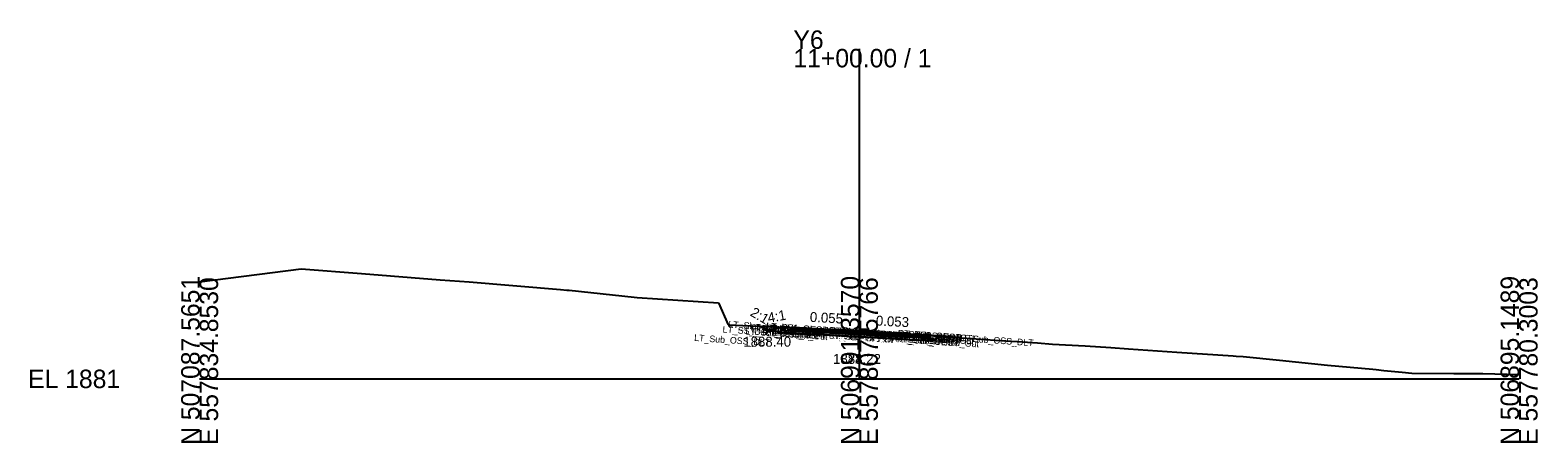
# Model space of a CAD drawing. Extents: x -26 to 203, y -10 to 1539.
# Drawn here: x -25.7 to 202.8, y 990.3 to 1052.8 of the extents above; entities that cross this region are included whole.
import ezdxf

# ---------------------------------------------------------------- set-up
doc = ezdxf.new("R2010")
doc.units = 0
for name, color, linetype in [('Default', 7, 'Continuous'), ('Exist Cross Section Cell', 7, 'Continuous'), ('Exist XS Center Line Elevation Label', 7, 'Continuous'), ('Exist XS Ground Line', 7, 'Continuous'), ('Prop CMT Pvmt Course 1', 7, 'Continuous'), ('Prop CMT Pvmt Course 2', 7, 'Continuous'), ('Prop CMT Pvmt Course 3', 7, 'Continuous'), ('Prop CMT Pvmt Surface', 7, 'Continuous'), ('Prop CMT Pvmt Surface Shoulder', 7, 'Continuous'), ('Prop CMT Shld Paved Course 1', 7, 'Continuous'), ('Prop CMT Shld Paved Course 2', 7, 'Continuous'), ('Prop CMT Shld Paved Course 3', 7, 'Continuous'), ('Prop CMT Slope Grass', 7, 'Continuous'), ('Prop CMT Subgrade Earthwork', 7, 'Continuous'), ('Prop XS Ditch Standard Text', 7, 'Continuous'), ('Prop XS Earthwork Shape', 7, 'Continuous'), ('Prop XS SE Text', 7, 'Continuous'), ('Prop XS Side Slope Text', 7, 'Continuous'), ('Typical Text Asphalt at Bridge Approach CELL', 7, 'Continuous')]:
    doc.layers.add(name, color=color, linetype=linetype)

msp = doc.modelspace()

# ---------------------------------------------------------------- linework, layer by layer
at = {"layer": 'Exist Cross Section Cell'}
for p, q in [((100, 1000), (100, 1050.01)), ((0, 1000), (100, 1000)), ((100, 1000), (200, 1000))]:
    msp.add_line(p, q, dxfattribs=at)
at = {"layer": 'Exist XS Ground Line'}
for p, q in [((0, 1014.72), (15.4, 1016.67)), ((15.4, 1016.67), (24.54, 1015.96)), ((24.54, 1015.96), (36.44, 1015.02)), ((36.44, 1015.02), (40.83, 1014.73)), ((40.83, 1014.73), (54.7, 1013.53)), ((54.7, 1013.53), (55.67, 1013.44)), ((55.67, 1013.44), (56, 1013.42)), ((56, 1013.42), (65.84, 1012.37)), ((65.84, 1012.37), (66.3, 1012.34)), ((66.3, 1012.34), (78.67, 1011.55)), ((78.67, 1011.55), (80.12, 1008.19)), ((80.12, 1008.19), (83.42, 1008.02)), ((83.42, 1008.02), (88.9, 1007.83)), ((88.9, 1007.83), (89.89, 1007.8)), ((89.89, 1007.8), (98.34, 1007.32)), ((98.34, 1007.32), (100, 1007.22)), ((100, 1007.22), (101.07, 1007.16)), ((101.07, 1007.16), (104.32, 1007.01)), ((104.32, 1007.01), (106.3, 1006.88)), ((106.3, 1006.88), (119.14, 1005.99)), ((119.14, 1005.99), (120.56, 1005.88)), ((120.56, 1005.88), (121.39, 1005.81)), ((121.39, 1005.81), (124.71, 1005.6)), ((124.71, 1005.6), (127, 1005.44)), ((127, 1005.44), (129.25, 1005.27)), ((129.25, 1005.27), (134.24, 1004.99)), ((134.24, 1004.99), (138.09, 1004.74)), ((138.09, 1004.74), (140.78, 1004.55)), ((140.78, 1004.55), (148.1, 1004.06)), ((148.1, 1004.06), (156.66, 1003.48)), ((156.66, 1003.48), (157.11, 1003.45)), ((157.11, 1003.45), (158.19, 1003.39)), ((158.19, 1003.39), (163.66, 1002.82)), ((163.66, 1002.82), (166.1, 1002.57)), ((166.1, 1002.57), (170.97, 1002.1)), ((170.97, 1002.1), (177.82, 1001.46)), ((177.82, 1001.46), (178.32, 1001.41)), ((178.32, 1001.41), (179.47, 1001.29)), ((179.47, 1001.29), (182.29, 1001)), ((182.29, 1001), (183.73, 1000.86)), ((183.73, 1000.86), (190.09, 1000.84)), ((190.09, 1000.84), (194.52, 1000.84)), ((194.52, 1000.84), (200, 1000.68))]:
    msp.add_line(p, q, dxfattribs=at)
at = {"layer": 'Prop CMT Pvmt Course 1'}
for points in [[(100, 1007.23), (90, 1007.79)], [(90, 1007.79), (90, 1007.54)], [(90, 1007.54), (100, 1006.98)], [(100, 1006.98), (100, 1007.23)], [(100, 1007.23), (110, 1006.7)], [(100, 1006.98), (100, 1007.23)], [(110, 1006.45), (100, 1006.98)], [(110, 1006.7), (110, 1006.45)]]:
    msp.add_lwpolyline(points, dxfattribs=at)
msp.add_lwpolyline([(100, 1006.98), (100, 1007.11), (100, 1007.11), (100, 1006.98)], close=True, dxfattribs=at)
msp.add_lwpolyline([(100, 1006.98), (100, 1007.11), (100, 1007.11), (100, 1006.98)], close=True, dxfattribs=at)
at = {"layer": 'Prop CMT Pvmt Course 2'}
for points in [[(100, 1006.98), (90, 1007.54)], [(90, 1007.54), (90, 1007.29)], [(90, 1007.29), (100, 1006.73)], [(100, 1006.73), (100, 1006.98)], [(100, 1006.73), (100, 1006.98)], [(100, 1006.98), (110, 1006.45)], [(110, 1006.2), (100, 1006.73)], [(110, 1006.45), (110, 1006.2)]]:
    msp.add_lwpolyline(points, dxfattribs=at)
at = {"layer": 'Prop CMT Pvmt Course 3'}
for points in [[(100, 1006.73), (90, 1007.29)], [(90, 1007.29), (90, 1006.91)], [(90, 1006.91), (100, 1006.36)], [(100, 1006.36), (100, 1006.73)], [(100, 1006.73), (110, 1006.2)], [(100, 1006.36), (100, 1006.73)], [(110, 1005.82), (100, 1006.36)], [(110, 1006.2), (110, 1005.82)]]:
    msp.add_lwpolyline(points, dxfattribs=at)
at = {"layer": 'Prop CMT Pvmt Surface'}
for points in [[(100, 1007.23), (90, 1007.79)], [(100, 1007.23), (110, 1006.7)]]:
    msp.add_lwpolyline(points, dxfattribs=at)
at = {"layer": 'Prop CMT Pvmt Surface Shoulder'}
for points in [[(90, 1007.79), (90, 1007.79)], [(110, 1006.7), (110, 1006.7)]]:
    msp.add_lwpolyline(points, dxfattribs=at)
at = {"layer": 'Prop CMT Shld Paved Course 1'}
for points in [[(90.06, 1007.78), (89.79, 1007.55)], [(89.79, 1007.55), (90.04, 1007.54)], [(90, 1007.79), (90, 1007.79)], [(90, 1007.54), (90, 1007.79)], [(110, 1006.7), (110, 1006.7)], [(110, 1006.7), (110.26, 1006.44)], [(110, 1006.45), (110, 1006.7)], [(110.26, 1006.44), (110, 1006.45)]]:
    msp.add_lwpolyline(points, dxfattribs=at)
at = {"layer": 'Prop CMT Shld Paved Course 2'}
for points in [[(90.04, 1007.54), (89.79, 1007.55), (89.52, 1007.31)], [(89.52, 1007.31), (90.03, 1007.29)], [(90, 1007.29), (90, 1007.54)], [(110, 1006.45), (110.26, 1006.44), (110.51, 1006.19)], [(110, 1006.2), (110, 1006.45)], [(110.51, 1006.19), (110, 1006.2)]]:
    msp.add_lwpolyline(points, dxfattribs=at)
at = {"layer": 'Prop CMT Shld Paved Course 3'}
for points in [[(90.03, 1007.29), (89.52, 1007.31), (89.02, 1007.33), (88.61, 1006.98)], [(88.61, 1006.98), (90, 1006.91)], [(90, 1006.91), (90, 1007.29)], [(110, 1006.2), (110.51, 1006.19), (111.01, 1006.18), (111.39, 1005.8)], [(110, 1005.82), (110, 1006.2)], [(111.39, 1005.8), (110, 1005.82)]]:
    msp.add_lwpolyline(points, dxfattribs=at)
at = {"layer": 'Prop CMT Slope Grass'}
msp.add_line((110, 1006.7), (112.33, 1006.46), dxfattribs=at)
msp.add_lwpolyline([(90.06, 1007.78), (88.05, 1007.76), (86.02, 1007.4), (85.07, 1007.96)], dxfattribs=at)
at = {"layer": 'Prop CMT Subgrade Earthwork'}
for p, q in [((88.61, 1006.98), (86.02, 1007.4)), ((111.39, 1005.8), (112.33, 1006.46))]:
    msp.add_line(p, q, dxfattribs=at)
for points in [[(90, 1006.91), (88.61, 1006.98)], [(100, 1006.36), (90, 1006.91)], [(100, 1006.36), (110, 1005.82)], [(110, 1005.82), (111.39, 1005.8)]]:
    msp.add_lwpolyline(points, dxfattribs=at)
at = {"layer": 'Prop XS Earthwork Shape'}
for points in [[(88.05, 1007.76), (86.02, 1007.4), (85.07, 1007.96), (88.9, 1007.83), (89.89, 1007.8), (90, 1007.79)], [(88.05, 1007.76), (86.02, 1007.4), (88.61, 1006.98), (90, 1006.91), (100, 1006.36), (110, 1005.82), (111.39, 1005.8), (112.33, 1006.46), (106.3, 1006.88), (104.75, 1006.98), (103.54, 1007.04), (101.07, 1007.16), (100, 1007.23), (98.34, 1007.32), (90, 1007.79)], [(104.32, 1007.01), (104.75, 1006.98), (103.54, 1007.04)]]:
    msp.add_lwpolyline(points, close=True, dxfattribs=at)

# ---------------------------------------------------------------- texts
at = {"layer": 'Default'}
msp.add_text('-', height=0.0001, dxfattribs=at).set_placement((0, 1000))
at = {"layer": 'Exist Cross Section Cell'}
for s, p in [('Y6', (90, 1050.01)), ('11+00.00 / 1', (90, 1047.21)), ('EL 1881', (-26, 998.6))]:
    msp.add_text(s, height=2.8, dxfattribs=at).set_placement(p)
for s, p in [('N 507087.5651', (0, 990)), ('E 557834.8530', (2.8, 990)), ('N 506991.3570', (100, 990)), ('E 557807.5766', (102.8, 990)), ('N 506895.1489', (200, 990)), ('E 557780.3003', (202.8, 990))]:
    msp.add_text(s, height=2.8, rotation=90, dxfattribs=at).set_placement(p)
at = {"layer": 'Exist XS Center Line Elevation Label'}
msp.add_text('1888.22', height=1.5, dxfattribs=at).set_placement((96.01, 1002.27))
at = {"layer": 'Prop XS Ditch Standard Text'}
msp.add_text('1888.40', height=1.5, dxfattribs=at).set_placement((82.4, 1004.88))
at = {"layer": 'Prop XS SE Text'}
for s, rotation, p in [('0.055', 356.8329, (92.46, 1008.65)), ('0.053', 356.9398, (102.47, 1008.1))]:
    msp.add_text(s, height=1.5, rotation=rotation, dxfattribs=at).set_placement(p)
at = {"layer": 'Prop XS Side Slope Text'}
for s, rotation, p in [('2:1', 329.5485, (83.33, 1009.66)), ('4:1', 10.1498, (86.23, 1008.5))]:
    msp.add_text(s, height=1.5, rotation=rotation, dxfattribs=at).set_placement(p)
at = {"layer": 'Typical Text Asphalt at Bridge Approach CELL'}
for s, p in [('LT_SS_Ditch_Base_Out', (79.24, 1007.04)), ('LT_Slope_Cut', (80.12, 1007.78)), ('LT_GS_OS_CTL', (83.44, 1007.39)), ('LT_PS3_Shelf_Out', (83.63, 1007.08)), ('LT_PS3_OEOP', (85.25, 1007.01)), ('LT_PS2_OEOP', (85.51, 1007.27)), ('LT_PV2_OEOT', (85.72, 1007.28)), ('LT_PV3_OEOT', (85.72, 1007.03)), ('LT_PV1_OEOT', (85.84, 1007.52)), ('LT_PS1_OEOP', (85.88, 1007.52)), ('RT_PV1_OEEOP', (95.43, 1006.87)), ('LT_PV1_OEEOP', (95.49, 1006.86)), ('RT_PV1_IEEOP', (95.81, 1006.84)), ('PV1_PGL', (97.44, 1006.85)), ('LT_Sub_OSS_DLT', (74.93, 1005.76)), ('LT_Sub_Trench_Out', (82.7, 1006.74)), ('LT_Sub_OEOT', (85.74, 1006.65)), ('RT_PV2_OEEOP', (95.31, 1006.75)), ('RT_PV3_OEEOP', (95.31, 1006.5)), ('RT_Sub_OEEOP', (95.33, 1006.13)), ('LT_PV2_OEEOP', (95.37, 1006.75)), ('LT_PV3_OEEOP', (95.37, 1006.5)), ('LT_Sub_OEEOP', (95.39, 1006.12)), ('RT_PV2_IEEOP', (95.69, 1006.73)), ('LT_PV2_IEEOP', (95.75, 1006.72)), ('LT_PV1_IEEOP', (95.87, 1006.84)), ('PV2_PGL', (97.32, 1006.61)), ('RT_Sub_Trench_Out', (105.42, 1005.65)), ('RT_PS3_Shelf_Out', (105.59, 1006)), ('RT_PV2_OEOT', (105.66, 1006.19)), ('RT_PV3_OEOT', (105.66, 1005.94)), ('RT_Sub_OEOT', (105.69, 1005.57)), ('RT_PV1_OEOT', (105.78, 1006.43)), ('RT_PS1_OEOP', (105.82, 1006.43)), ('RT_PS2_OEOP', (105.96, 1006.18)), ('RT_PS3_OEOP', (106.21, 1005.93)), ('RT_GS_OS_CTL', (107.38, 1006.3)), ('RT_Sub_OSS_DLT', (114.66, 1005.77))]:
    msp.add_text(s, height=1, rotation=356, dxfattribs=at).set_placement(p)

doc.saveas('drawing.dxf')
